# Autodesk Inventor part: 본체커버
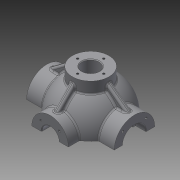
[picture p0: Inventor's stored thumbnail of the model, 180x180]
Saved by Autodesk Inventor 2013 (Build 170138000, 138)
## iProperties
Created: 2015-12
Part Number: 본체커버
Material: 일반
Document SubType Name: Modeling
Designer: mduedu
Density: 2.71 g/cm^3
Mass: 589.734 g
Surface Area: 460.056 cm^2
Volume: 217.614 cm^3
Author: mduedu
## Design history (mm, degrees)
sketch "스케치1"
  geometry: L1 (-53, 0)-(53, 0); A1 r 53 centre (0, 0) between (53, 0) and (-53, 0); 2 further points
  constraints: 2 coincident, 2 end point, 2 point on circle, 1 centre point, 1 horizontal, 1 midpoint
  dimensions: "d0" = 53 radius of A1
revolve "회전1" sketch "스케치1" stored, may be unused: angle "d2" = 90 deg
feature "쉘1" dims "d11" = 10
node "작업 평면1"
sketch "스케치2"
  geometry: C1 r 31 at (0, 0); 1 further point
  constraints: 1 centre point, 1 coincident
  dimensions: "d4" = 62 diameter of C1
extrude "돌출1" join sketch "스케치2" stored distance "d5" = 10; taper "d6" = 0 deg
node "작업 평면2"
sketch "스케치3"
  geometry: C1 r 28 at (0, 0); 1 further point
  constraints: 1 centre point, 1 coincident
  dimensions: "d8" = 56 diameter of C1
extrude "돌출2" join sketch "스케치3" stored distance "d9" = 10; taper "d10" = 0 deg
hole "구멍1" diameter "d14" = 35; stored, may be unused: countersink angle "d18" = 90 deg, drill point angle "d20" = 0 deg; dims "d12" = 10, "d13" = 10, "d15" = 6, "d16" = 4, "d17" = 2, "d19" = 16
hole "구멍2" diameter "d23" = 27; stored, may be unused: countersink angle "d27" = 90 deg, drill point angle "d29" = 0 deg; dims "d21" = 10, "d22" = 10, "d24" = 6, "d25" = 4, "d26" = 2, "d28" = 16
fillet "모깎기1" dims "d30" = 0.3
hole "구멍3" diameter "d33" = 26; stored, may be unused: countersink angle "d37" = 90 deg, drill point angle "d39" = 0 deg; dims "d31" = 10, "d32" = 10, "d34" = 6, "d35" = 4, "d36" = 2, "d38" = 16
chamfer "모따기1" distance "d40" = 1; stored, may be unused: second distance "d41" = 2, angle "d42" = 45 deg
sketch "스케치4"
  geometry: L1 (0, 0)-(0, -25); L2 (0, 0)-(-17.678, -17.678); A1 r 25 centre (0, 0) between (-17.678, -17.678) and (0, -25); 1 further point
  constraints: 4 end point, 2 point on circle, 1 centre point, 1 coincident, 1 vertical
  dimensions: "d43" = 50 diameter of A1; "d47" = 45 deg angle of L1 L2
hole "구멍4" sketch "스케치4" at (-17.678, -17.678) diameter "d49" = 3.242; stored, may be unused: countersink angle "d53" = 90 deg, drill point angle "d55" = 118 deg; dims "d50" = 11, "d51" = 4, "d52" = 2, "d54" = 13
sketch "스케치5"
  geometry: L1 (0, 0)-(0, -20); L2 (0, 0)-(-14.142, -14.142); A1 r 20 centre (0, 0) between (0, -20) and (-14.142, -14.142); 2 further points
  constraints: 4 end point, 2 coincident, 2 point on circle, 1 centre point, 1 vertical
  dimensions: "d59" = 40 diameter of A1; "d65" = 45 deg angle of L1 L2
hole "구멍5" sketch "스케치5" at (-14.142, -14.142) diameter "d67" = 3.242; stored, may be unused: countersink angle "d71" = 90 deg, drill point angle "d73" = 118 deg; dims "d68" = 8, "d69" = 4, "d70" = 2, "d72" = 10
node "작업 평면3"
sketch "스케치6"
  geometry: C1 r 65 at (0, 0); 1 further point
  constraints: 1 centre point, 1 coincident
  dimensions: "d78" = 130 diameter of C1
extrude "돌출3" join sketch "스케치6" distance "d80" = 10; taper "d81" = 0 deg
sketch "스케치7"
  geometry: C1 r 20 at (0, 0); 1 further point
  constraints: 1 centre point, 1 coincident
  dimensions: "d82" = 40 diameter of C1
extrude "돌출4" join sketch "스케치7" stored distance "d84" = 10; taper "d85" = 0 deg
sketch "스케치8"
  geometry: 2 further points
  constraints: 1 coincident
hole "구멍6" sketch "스케치8" at (0, 0) diameter "d86" = 20; stored, may be unused: countersink angle "d90" = 90 deg, drill point angle "d92" = 118 deg; dims "d87" = 7, "d88" = 40, "d89" = 5, "d91" = 10
fillet "모깎기2" dims "d93" = 0.3
sketch "스케치9"
  geometry: L1 (65, -75)-(-65, -75) reference; L2 (-45, -75)-(-38.245, -36.692); A1 r 53 centre (0, 0) between (42.988, 31) and (42.988, -31) reference; 1 further point
  constraints: 2 end point, 1 point on circle, 1 point on line
  dimensions: "d94" = 45 horizontal distance of L2.start point (0, 0); "d95" = 80 deg angle of L2 L1
feature "리브1" sketch "스케치9" dims "d96" = 1, "d97" = 8, "d98" = 0, "d99" = 0, "d100" = 1, "d101" = 1
sketch "스케치10"
  geometry: L1 (0, 0)-(0, -55); L2 (0, 0)-(-38.891, -38.891); A1 r 55 centre (0, 0) between (0, -55) and (-38.891, -38.891); 2 further points
  constraints: 4 end point, 2 coincident, 2 point on circle, 1 centre point, 1 vertical
  dimensions: "d105" = 110 diameter of A1; "d107" = 45 deg angle of L1 L2
hole "구멍7" sketch "스케치10" at (-38.891, -38.891) diameter "d109" = 10; stored, may be unused: countersink angle "d113" = 90 deg, drill point angle "d115" = 118 deg; dims "d110" = 7, "d111" = 40, "d112" = 5, "d114" = 10
fillet "모깎기3" dims "d120" = 3
fillet "모깎기4" dims "d121" = 3, "d122" = 3
fillet "모깎기5" dims "d123" = 3
fillet "모깎기6" dims "d124" = 3
sketch "스케치11"
  geometry: C1 r 5 at (-38.891, 38.891) reference; C2 r 5 at (38.891, 38.891) reference; C3 r 5 at (38.891, -38.891) reference; C4 r 5 at (-38.891, -38.891) reference; C5 r 20 at (0, 0) reference; C6 r 65 at (0, 0) reference; 1 further point
  constraints: 3 other
feature "엠보싱1" sketch "스케치11" dims "d125" = 0.5, "d126" = 0
sketch "스케치12"
  geometry: L1 (0, 100)-(0, -100); L2 (0, 100)-(-150, 100); L3 (-150, 100)-(-150, -100); L4 (-150, -100)-(0, -100); 2 further points
  constraints: 8 end point, 3 perpendicular, 1 coincident, 1 midpoint, 1 vertical
  dimensions: "d127" = 200 distance of L2.end L3.end; "d129" = 150 distance of L3.end L1.end
extrude "돌출5" cut sketch "스케치12" stored distance "d130" = 10; taper "d131" = 0 deg
sketch "스케치13"
  geometry: C1 r 7 at (0, -53); A1 r 53 centre (0, 0) between (-42.113, -32.179) and (42.113, -32.179) reference; 1 further point
  constraints: 1 centre point, 1 point on circle
  dimensions: "d132" = 14 diameter of C1
extrude "돌출6" join sketch "스케치13" distance "d133" = 5; taper "d134" = 0 deg
sketch "스케치14"
  geometry: C1 r 7 at (0, 0) reference; 1 further point
extrude "돌출7" cut sketch "스케치14" stored distance "d135" = 5; taper "d136" = 0 deg
sketch "스케치15"
  geometry: C1 r 2.25 at (0, 53); A1 r 7 centre (0, 53) between (6.965, 52.302) and (-6.965, 52.302) reference; 1 further point
  constraints: 1 centre point, 1 coincident
  dimensions: "d139" = 4.5 diameter of C1
extrude "돌출8" cut sketch "스케치15" stored distance "d141" = 5; taper "d142" = 0 deg
fillet "모깎기7" dims "d143" = 3
fillet "모깎기8" dims "d144" = 1
fillet "모깎기9" dims "d145" = 1
fillet "모깎기10" dims "d146" = 1
node "작업 평면4"
sketch "스케치16"
  geometry: C1 r 28 at (0, 0); 1 further point
  constraints: 1 centre point, 1 coincident
  dimensions: "d148" = 56 diameter of C1
extrude "돌출9" join sketch "스케치16" stored distance "d150" = 5; taper "d151" = 0 deg
hole "구멍8" diameter "d154" = 26; stored, may be unused: countersink angle "d158" = 90 deg, drill point angle "d160" = 118 deg; dims "d152" = 10, "d153" = 10, "d155" = 6, "d156" = 4, "d157" = 2, "d159" = 8
sketch "스케치17" dims "d161" = 40
  geometry: 3 further points
  constraints: 2 vertical alignment, 1 coincident, 2 other
hole "구멍9" sketch "스케치17" at (0, 20) diameter "d163" = 3.242; stored, may be unused: countersink angle "d167" = 90 deg, drill point angle "d169" = 118 deg; dims "d164" = 8, "d165" = 4, "d166" = 2, "d168" = 10
fillet "모깎기11" dims "d173" = 3
chamfer "모따기2" distance "d174" = 1; stored, may be unused: second distance "d175" = 2, angle "d176" = 45 deg
sketch "스케치18"
  geometry: L1 (28, 62)-(28, 46.637) reference; L2 (67, 31)-(44.497, 31) reference; L3 (28, 55)-(60, 31); L4 (-28, 62)-(28, 62) reference; L5 (67, 31)-(67, 0) reference; 1 further point
  constraints: 2 end point, 2 point on line
  dimensions: "d177" = 7 distance from line of L3.start L4; "d178" = 7 distance from line of L3.end L5
feature "리브2" sketch "스케치18" dims "d179" = 1, "d180" = 8, "d181" = 0, "d182" = 0, "d183" = 1, "d184" = 1
fillet "모깎기12" dims "d185" = 3
fillet "모깎기13" dims "d186" = 3
sketch "스케치19"
  geometry: L1 (62, 28)-(46.637, 28) reference; L2 (28, 62)-(28, 46.637) reference; L3 (55, 28)-(28, 55); L4 (0, 62)-(28, 62) reference; L5 (62, 28)-(62, -28) reference; 1 further point
  constraints: 2 end point, 2 point on line
  dimensions: "d187" = 7 distance from line of L3.end L4; "d188" = 7 distance from line of L3.start L5
feature "리브3" sketch "스케치19" dims "d189" = 1, "d190" = 8, "d191" = 0, "d192" = 0, "d193" = 1, "d194" = 1
fillet "모깎기14" dims "d195" = 3
fillet "모깎기15" dims "d196" = 3
node "솔리드1"
mirror "대칭1"
mirror "대칭2"
pattern_circular "원형 패턴1" dims angle "d57" = 360 deg
mirror "대칭3"
pattern_circular "원형 패턴2" dims angle "d75" = 360 deg
pattern_circular "원형 패턴3" dims angle "d103" = 360 deg
pattern_circular "원형 패턴4" dims angle "d118" = 360 deg
pattern_circular "원형 패턴5" dims angle "d171" = 360 deg
mirror "대칭4"
node "투영된 루프1"
other parameters: "d3" = 67, "d7" = 62, "d77" = -85, "d147" = 62
